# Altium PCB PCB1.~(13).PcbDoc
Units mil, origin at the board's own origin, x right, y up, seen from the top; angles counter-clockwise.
Board outline 6000 x 4000 mil, 2 copper layers (Top Layer, Bottom Layer); 32 components, 21 nets, 142 pads, 0 vias.
Unrouted connection lines stored in the file: 66.
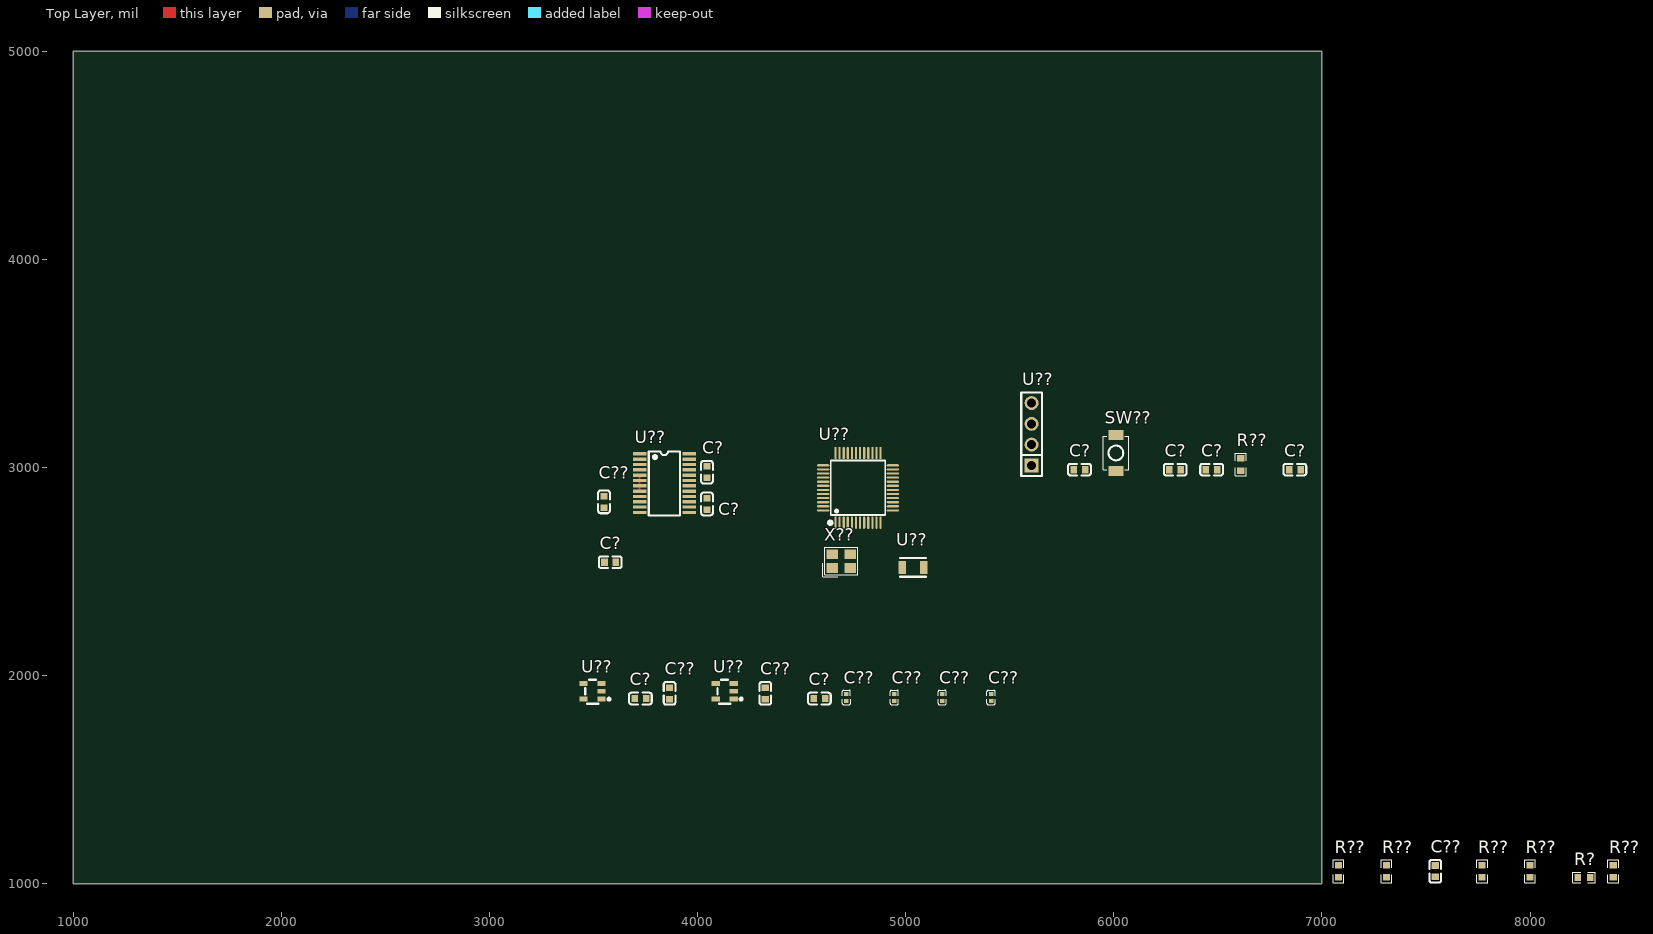
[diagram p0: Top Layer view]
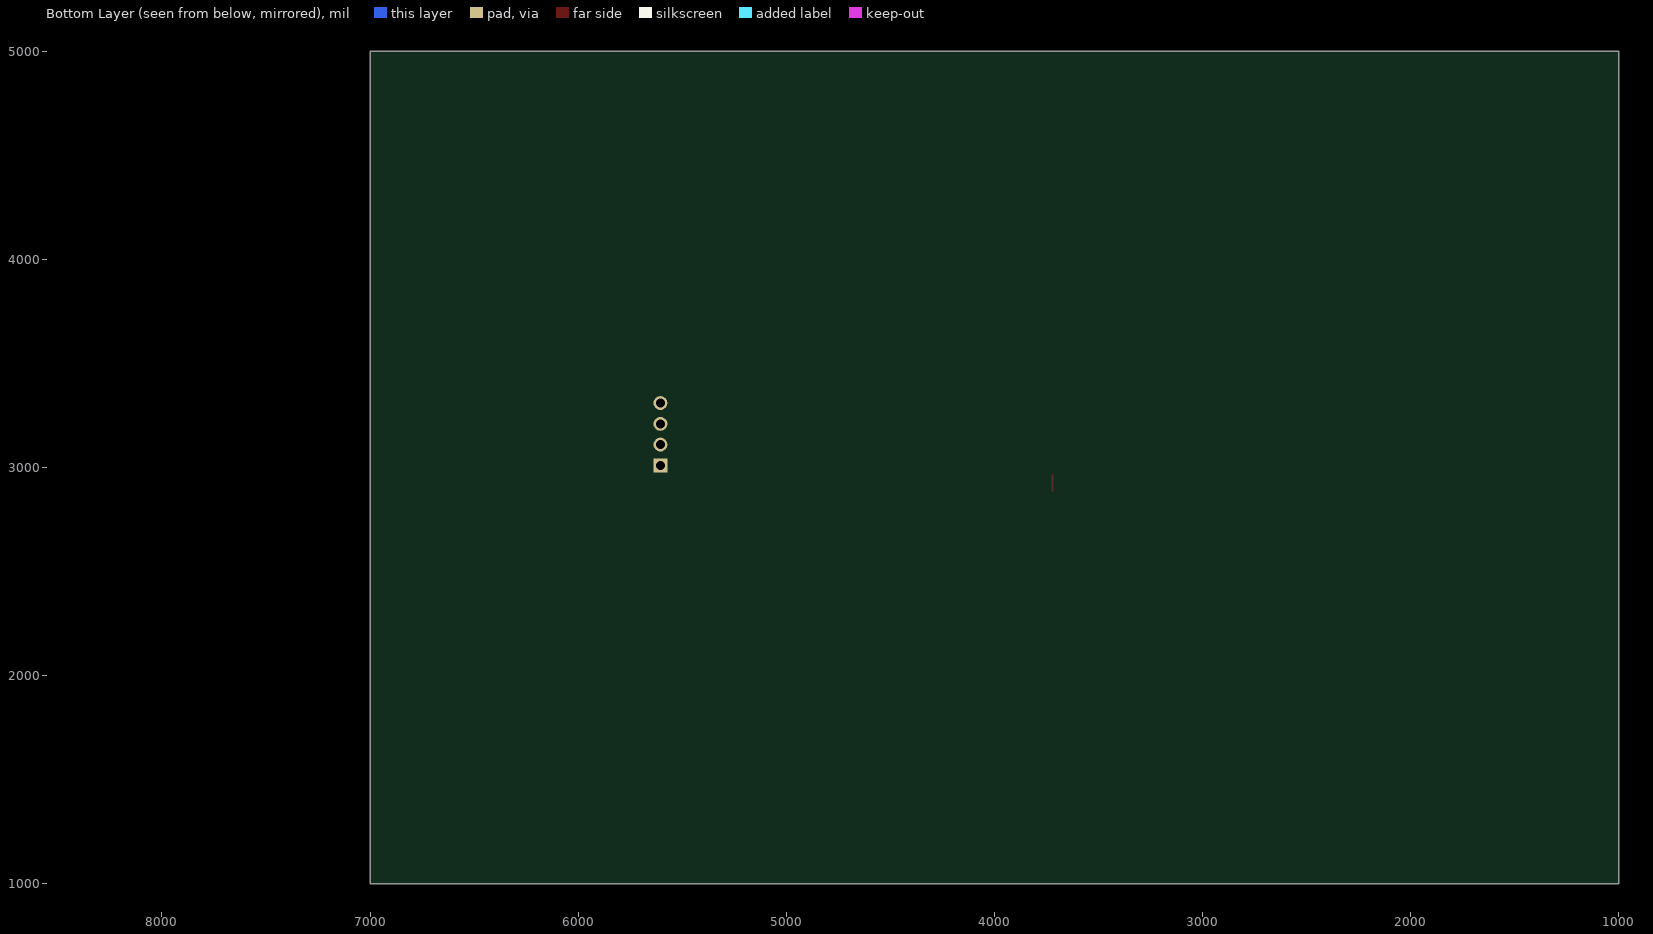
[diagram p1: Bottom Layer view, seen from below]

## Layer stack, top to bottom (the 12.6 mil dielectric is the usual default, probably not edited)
Top Solder: solder mask 0.4, Solder Resist, Dk 3.5
Top Layer: signal copper 1.4
Dielectric 1: dielectric 12.6, FR-4, Dk 4.8
Bottom Layer: signal copper 1.4
Bottom Solder: solder mask 0.4, Solder Resist, Dk 3.5

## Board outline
1000,1000 7000,1000 7000,5000 1000,5000

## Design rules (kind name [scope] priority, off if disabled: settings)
Clearance [All] p1: gap=10 ignorepadtopadclearanceinfootprint=FALSE
PolygonConnect [All] p1: connectstyle=Relief reliefconductorwidth=10 reliefentries=4 polygonreliefangle="90 Angle" airgapwidth=10
RoutingVias [All] p1: holewidth=28 width=50 viastyle="Through Hole" minholewidth=28 minwidth=50 maxholewidth=28 maxwidth=50
SolderMaskExpansion [All] p1: expansion=0 istentingtop=FALSE
SupplyNets "Schematic Supply Nets" [InNet('3V3')] p1: voltage=0.000
SupplyNets "Schematic Supply Nets_6" [InNet('+6')] p2: voltage=0.000
SupplyNets "Schematic Supply Nets_4" [InNet('5V')] p3: voltage=0.000
SupplyNets "Schematic Supply Nets_3" [InNet('DGND')] p4: voltage=0.000
SupplyNets "Schematic Supply Nets_1" [InNet('AGND')] p5: voltage=0.000
Width [All] p1: maxlimit=10 minlimit=10 preferedwidth=10
30 further rules are at their usual default settings.

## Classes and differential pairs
component class Sheet1: C? C?? R? R?? SW?? U?? X??

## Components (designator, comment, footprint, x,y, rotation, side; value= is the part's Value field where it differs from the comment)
C? "cga0603x7r104k500jt" C0603 6295,2990 r0 top value=100nF
C? "cga0603x7r104k500jt" C0603 5835,2990 r0 top value=100nF
C? "cga0603x7r104k500jt" C0603 6870,2990 r0 top value=100nF
C? "cga0603x7r104k500jt" C0603 6470,2990 r0 top value=100nF
C? "cga0603x5r105k500jt" C0603 4585,1890 r0 top value=1uF
C? "cga0603x5r105k500jt" C0603 3725,1890 r0 top value=1uF
C? "cga0603x7r104k500jt" C0603 4045,2825 r90 top value=100nF
C? "fcc0603b103k500ct" C0603 3580,2545 r0 top value=10nF
C? "cga0603x7r104k500jt" C0603 4045,2977.56 r90 top value=100nF
C?? "fcc0603b103k500ct" C0603 7545,1060 r90 top value=10nF
C?? "cga0603x5r105k500jt" C0603 3865,1915 r90 top value=1uF
C?? "cga0603x5r105k500jt" C0603 4325,1915 r90 top value=1uF
C?? "cc0402jrnpo9bn220" C0402 5410,1895 r90 top value=22pF
C?? "cc0402jrnpo9bn220" C0402 5175,1895 r90 top value=22pF
C?? "cc0402jrnpo9bn180" C0402 4715,1895 r90 top value=18pF
C?? "cc0402jrnpo9bn180" C0402 4945,1895 r90 top value=18pF
C?? "cga0603x7r104k500jt" C0603 3550,2835 r90 top value=100nF
R? "0603waf470jt5e" R0603 8260,1030 r0 top value=47Ω
R?? "frc0603f1000ts" R0603 7310,1060 r90 top value=100Ω
R?? "frc0603f1000ts" R0603 7770,1060 r90 top value=100Ω
R?? "0603waf470jt5e" R0603 8000,1060 r90 top value=47Ω
R?? "0603waf470jt5e" R0603 8400,1060 r90 top value=47Ω
R?? "0603waf0000t5e" R0603 7080,1060 r90 top value=0Ω
R?? "frc0603f1002ts" R0603 6610,3015 r90 top value=10kΩ
SW?? "ts-1088-ar02016" SW-SMD_L3.9-W3.0-P4.45 6010,3070 r90 top
U?? "hx pz2.54-1x4p zz" HDR-TH_4P-P2.54-V-M 5605,3160 r90 top
U?? "tps7a2050pdbvr" SOT-23-5_L2.9-W1.6-P0.95-LS2.8-BR 3495,1925 r0 top
U?? "tps7a2033pdbvr" SOT-23-5_L2.9-W1.6-P0.95-LS2.8-BR 4130,1925 r0 top
U?? "fc31m2-32.768-ntlnndtl" CRYSTAL-SMD_L3.2-W1.5 5035,2520 r0 top value=32.768kHz
U?? "stm32g031c8t6" LQFP-48_L7.0-W7.0-P0.50-LS9.0-BL 4770.79,2902.32 r0 top
U?? "ads1232ipwr" TSSOP-24_L7.8-W4.4-P0.65-LS6.4-BL 3840,2925 r270 top
X?? "x32258mob4si" CRYSTAL-SMD_4P-L3.2-W2.5-BL 4690,2550 r0 top value=8MHz

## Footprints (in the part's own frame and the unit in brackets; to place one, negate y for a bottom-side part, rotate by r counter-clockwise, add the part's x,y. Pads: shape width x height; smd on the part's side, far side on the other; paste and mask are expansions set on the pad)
C0402 [mm]
  rect 0.5x0.54 smd: 1(-0.42,0) 2(0.42,0)
  silkscreen extent -0.87,-0.5 0.87,0.5
C0603 [mm]
  rect 0.8x0.9 smd: 1(-0.7,0) 2(0.7,0)
  silkscreen extent -1.39,-0.71 1.39,0.71
CRYSTAL-SMD_4P-L3.2-W2.5-BL [mm]
  rect 1.4x1.2 smd: 1(-1.1,-0.85) 2(1.1,-0.85) 3(1.1,0.85) 4(-1.1,0.85)
  silkscreen extent -2.26,-1.91 2.03,1.68
CRYSTAL-SMD_L3.2-W1.5 [mm]
  rect 0.95x1.6 smd: 1(-1.308,0) 2(1.308,0)
  silkscreen extent -1.6,-1.14 1.6,1.14
HDR-TH_4P-P2.54-V-M [mm]
  rect 1.7x1.7 hole 1.1: 1(-3.81,0)
  round 1.7 hole 1.1: 2(-1.27,0) 3(1.27,0) 4(3.81,0)
  silkscreen extent -5.08,-1.27 5.08,1.27
LQFP-48_L7.0-W7.0-P0.50-LS9.0-BL [mm]
  oval 0.27x1.5 smd paste+0 mask+0.05: 1(-2.75,-4.25) 2(-2.25,-4.25) 3(-1.75,-4.25) 4(-1.25,-4.25) 5(-0.75,-4.25) 6(-0.25,-4.25) 7(0.25,-4.25) 8(0.75,-4.25) 9(1.25,-4.25) 10(1.75,-4.25) 11(2.25,-4.25) 12(2.75,-4.25) 25(2.75,4.25) 26(2.25,4.25) 27(1.75,4.25) 28(1.25,4.25) 29(0.75,4.25) 30(0.25,4.25) 31(-0.25,4.25) 32(-0.75,4.25) 33(-1.25,4.25) 34(-1.75,4.25) 35(-2.25,4.25) 36(-2.75,4.25)
  oval 1.5x0.27 smd paste+0 mask+0.05: 13(4.25,-2.75) 14(4.25,-2.25) 15(4.25,-1.75) 16(4.25,-1.25) 17(4.25,-0.75) 18(4.25,-0.25) 19(4.25,0.25) 20(4.25,0.75) 21(4.25,1.25) 22(4.25,1.75) 23(4.25,2.25) 24(4.25,2.75) 37(-4.25,2.75) 38(-4.25,2.25) 39(-4.25,1.75) 40(-4.25,1.25) 41(-4.25,0.75) 42(-4.25,0.25) 43(-4.25,-0.25) 44(-4.25,-0.75) 45(-4.25,-1.25) 46(-4.25,-1.75) 47(-4.25,-2.25) 48(-4.25,-2.75)
  silkscreen extent -3.59,-4.46 3.3,3.34
R0603 [mil]
  rect 31.75x34.02 smd paste-3937.01 mask+2: 1(-29.66,0) 2(29.66,0)
  silkscreen extent -55,-26 55,26
SOT-23-5_L2.9-W1.6-P0.95-LS2.8-BR [mm]
  rect 1x0.6 smd paste+0 mask+0.05: 1(1.1,-0.95) 2(1.1,0) 3(1.1,0.95) 4(-1.1,0.95) 5(-1.1,-0.95)
  silkscreen extent -0.89,-1.52 2.16,1.4
SW-SMD_L3.9-W3.0-P4.45 [mm]
  rect 1.23x1.86 smd: 1(-2.185,0) 2(2.185,0)
  silkscreen extent -2.03,-1.54 2.03,1.54
TSSOP-24_L7.8-W4.4-P0.65-LS6.4-BL [mm]
  rect 0.4x1.65 smd: 1(-3.575,-3.023) 2(-2.925,-3.023) 3(-2.275,-3.023) 4(-1.625,-3.023) 5(-0.975,-3.023) 6(-0.325,-3.023) 7(0.325,-3.023) 8(0.975,-3.023) 9(1.625,-3.023) 10(2.275,-3.023) 11(2.925,-3.023) 12(3.575,-3.023) 13(3.575,3.023) 14(2.925,3.023) 15(2.275,3.023) 16(1.625,3.023) 17(0.975,3.023) 18(0.325,3.023) 19(-0.325,3.023) 20(-0.975,3.023) 21(-1.625,3.023) 22(-2.275,3.023) 23(-2.925,3.023) 24(-3.575,3.023)
  silkscreen extent -3.89,-1.91 3.94,1.91

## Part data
C? C? C? C? C? C? C??: "容值:100nF;精度:±10%;额定电压:50V;温度系数:X7R;", JLCPCB Part Class="Extended Part", LCSC Part Name="100nF ±10% 50V", Manufacturer=HRE(芯声), ManufacturerPart=CGA0603X7R104K500JT, Temperature Coefficient=X7R, Tolerance=±10%, Voltage Rating=50V
C? C? C?? C??: "容值:1uF;精度:±10%;额定电压:50V;温度系数:X5R;", JLCPCB Part Class="Extended Part", LCSC Part Name="1uF ±10% 50V 停产", Manufacturer=HRE(芯声), ManufacturerPart=CGA0603X5R105K500JT, Temperature Coefficient=X5R, Tolerance=±10%, Voltage Rating=50V
C? C??: "容值:10nF;精度:±10%;额定电压:50V;温度系数:X7R;", JLCPCB Part Class="Extended Part", LCSC Part Name="10nF ±10% 50V", Manufacturer=FOJAN(富捷), ManufacturerPart=FCC0603B103K500CT, Operating Temperature=-55℃~+125℃, Temperature Coefficient=X7R, Tolerance=±10%, Voltage Rating=50V
C?? C??: "容值:22pF;精度:±5%;额定电压:50V;温度系数:NP0;", JLCPCB Part Class="Extended Part", LCSC Part Name="22pF ±5% 50V", Manufacturer=YAGEO(国巨), ManufacturerPart=CC0402JRNPO9BN220, Temperature Coefficient=NP0, Tolerance=±5%, Voltage Rating=50V
C?? C??: "容值:18pF;精度:±5%;额定电压:50V;温度系数:NP0;", JLCPCB Part Class="Extended Part", LCSC Part Name="18pF ±5% 50V", Manufacturer=YAGEO(国巨), ManufacturerPart=CC0402JRNPO9BN180, Temperature Coefficient=NP0, Tolerance=±5%, Voltage Rating=50V
R? R?? R??: "电阻类型:厚膜电阻;阻值:47Ω;精度:±1%;功率:100mW;工作电压:75V;温度系数:±100ppm/℃;", JLCPCB Part Class="Basic Part", LCSC Part Name="47Ω ±1% 100mW 厚膜电阻", Manufacturer=UNI-ROYAL(厚声), ManufacturerPart=0603WAF470JT5E, Operating Temperature=-55℃~+155℃, Power(Watts)=100mW, Temperature Coefficient=±100ppm/℃, Tolerance=±1%, Voltage-Supply(Max)=75V
R?? R??: "电阻类型:厚膜电阻;阻值:100Ω;精度:±1%;功率:100mW;工作电压:75V;温度系数:±100ppm/℃;", JLCPCB Part Class="Extended Part", LCSC Part Name="100Ω ±1% 100mW 厚膜电阻", Manufacturer=FOJAN(富捷), ManufacturerPart=FRC0603F1000TS, Operating Temperature=-55℃~+155℃, Power(Watts)=100mW, Temperature Coefficient=±100ppm/℃, Tolerance=±1%, Voltage-Supply(Max)=75V
R??: "电阻类型:厚膜电阻;阻值:0Ω;精度:±1%;功率:100mW;工作电压:75V;温度系数:-;", JLCPCB Part Class="Basic Part", LCSC Part Name="0Ω ±1% 100mW 厚膜电阻", Manufacturer=UNI-ROYAL(厚声), ManufacturerPart=0603WAF0000T5E, Operating Temperature=-55℃~+155℃, Power(Watts)=100mW, Temperature Coefficient=-, Tolerance=±1%, Voltage-Supply(Max)=75V
R??: "电阻类型:厚膜电阻;阻值:10kΩ;精度:±1%;功率:100mW;工作电压:75V;温度系数:±100ppm/℃;", JLCPCB Part Class="Extended Part", LCSC Part Name="10kΩ ±1% 100mW 厚膜电阻", Manufacturer=FOJAN(富捷), ManufacturerPart=FRC0603F1002TS, Operating Temperature=-55℃~+155℃, Power(Watts)=100mW, Temperature Coefficient=±100ppm/℃, Tolerance=±1%, Voltage-Supply(Max)=75V
SW??: "电路结构:单刀单掷;按钮形状:圆形按钮;作用力:1.6N;安装方式:立贴;开关长度:3.9mm;开关宽度:3mm;开关高度:2mm;带支架:不带支架;触点电流:50mA;额定电压:12V;带灯:-;工作寿命:10万次;", Actuator/Cap Color=黑色, Contact Current=50mA, IP Rating=-, JLCPCB Part Class="Basic Part", LCSC Part Name="3.9*3*2mm 立贴 轻触开关", Manufacturer=XUNPU(讯普), ManufacturerPart=TS-1088-AR02016, Operating Force=1.6N, Operating Temperature=-30℃~+80℃, Voltage Rating=12V
U??: "插针结构:1x4P;间距:2.54mm;行距:-;圆针/方针:方针;安装方式:直插;排数:单排;总PIN位数:4P;额定电流:3A;额定电压:1kV;配合针长度:6mm;塑高:2.5mm;端接针长度:3mm;触头材质:黄铜;触头镀层:金;工作温度:-40℃~+105℃;颜色:黑色;", Color=黑色, Current Rating=3A, JLCPCB Part Class="Extended Part", LCSC Part Name="1x4P 间距:2.54mm 方针 直插", Manufacturer=hanxia(韩下), ManufacturerPart="HX PZ2.54-1x4P ZZ", Operating Temperature=-40℃~+105℃, Voltage Rating (Max)=1kV
U??: "输出极性:正极;工作电压:6V;输出电压:5V;输出电流:300mA;电源纹波抑制比(PSRR):65dB@(100Hz);输出类型:固定;", JLCPCB Part Class="Extended Part", LCSC Part Name="800mV~5.5V 300mA 6V", Manufacturer=TI(德州仪器), ManufacturerPart=TPS7A2050PDBVR, Operating Temperature=-40℃~+125℃@(Tj), Output Current=300mA, Output Voltage=5V, Power Supply Rejection Ratio (PSRR)=65dB@(100Hz), standby current=6.5uA, Voltage - Supply=6V, Voltage Dropout=140mV@(300mA)
U??: "输出类型:固定;最大输入电压:6V;输出电压:3.3V;输出电流:300mA;输出极性:正极;", Dropout Voltage=140mV@(300mA), JLCPCB Part Class="Extended Part", LCSC Part Name="具有高 PSRR 的 300mA、超低噪声、低 IQ、低压降 (LDO) 线性稳压器", Manufacturer=TI(德州仪器), ManufacturerPart=TPS7A2033PDBVR, Maximum Input Voltage=6V, Operating Temperature=-40℃~+125℃@(Tj), Output Current=300mA, Output Voltage=3.3V, standby current=15uA
U??: "晶振类型:贴片晶振;频率:32.768kHz;常温频差:±10ppm;负载电容:12.5pF;频率稳定度:±10ppm;", Equivalent Series Resistance(ESR)=70kΩ, Frequency Stability=±10ppm, JLCPCB Part Class="Extended Part", LCSC Part Name="3215 2P 32.768kHz 12.5pF ±10ppm -40~+85℃(±10ppm)", Load Capacitance=12.5pF, Manufacturer=HCI(杭晶), ManufacturerPart=FC31M2-32.768-NTLNNDTL, Operating Temperature=-40℃~+85℃
U??: "CPU内核:ARM Cortex-M0+;CPU最大主频:64MHz;CPU位数:32 Bit;", JLCPCB Part Class="Extended Part", LCSC Part Name="主流Arm Cortex-M0+ MCU，具有64 KB Flash存储器、8 KB RAM、64 MHz CPU、2x USART、定时器、ADC和通信接口，1.7-3.6V", Manufacturer=ST(意法半导体), ManufacturerPart=STM32G031C8T6, Operating Temperature=-40℃~+85℃, Voltage - Supply=1.7V~3.6V
U??: "分辨率(位):24;采样率:10Hz;工作电压:2.7V~5.3V;接口类型:SPI;", Clock Frequency=4.9152MHz；200kHz~8MHz, JLCPCB Part Class="Extended Part", LCSC Part Name="用于桥式传感器的24bit 模数转换器", Manufacturer=TI(德州仪器), ManufacturerPart=ADS1232IPWR, Operating Temperature=-40℃~+105℃, Quiescent Current (Iq)=1.3uA, Temperature Sensors=内置, Voltage - Supply=2.7V~5.3V, Voltage Reference=外置, Voltage Reference Drift=-
X??: "晶振类型:贴片晶振;频率:8MHz;常温频差:±10ppm;负载电容:12pF;频率稳定度:±20ppm;", Equivalent Series Resistance(ESR)=180Ω, Frequency Stability=±20ppm, JLCPCB Part Class="Extended Part", LCSC Part Name="YSX321SL 8MHZ 4P 3225 12PF ±10PPM -40~85℃ (±20PPM)", Load Capacitance=12pF, Manufacturer=YXC(扬兴晶振), ManufacturerPart=X32258MOB4SI, Normal temperature Frequency Tolerance=±10ppm, Operating Temperature=-40℃~+85℃

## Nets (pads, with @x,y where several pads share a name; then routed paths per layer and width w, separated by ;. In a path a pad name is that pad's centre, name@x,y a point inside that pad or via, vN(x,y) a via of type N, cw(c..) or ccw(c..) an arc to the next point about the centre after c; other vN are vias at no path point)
3V3: C?.1@4045,2950 C?.1@4557.44,1890 C?.2@5862.56,2990 C?.2@6497.56,2990 C?.2@6897.56,2990 R??.2@6610,3044.66 U??.1@3721,3065.74 U??.1@5605,3010 U??.4@4721.58,2735 U??.5@4086.69,1887.6 U??.5@4741.26,2735 U??.6@4760.95,2735 U??.19@3959,2937.79 U??.20@3959,2963.38
5V: C?.1@3552.44,2545 C?.1@3697.44,1890 C?.2@4045,2852.56 U??.5@3451.69,1887.6 U??.16@3959,2861.02 U??.18@3959,2912.21
+6: C??.1@3865,1887.44 C??.1@4325,1887.44 U??.1@3538.31,1887.61 U??.1@4173.31,1887.61 U??.3@3538.31,1962.39 U??.3@4173.31,1962.39
AGND: C?.1@4045,2797.44 C?.2@3607.56,2545 R??.1@7080,1030.34 U??.13@3959,2784.26 U??.14@3959,2809.84 U??.15@3959,2835.43 U??.17@3959,2886.61
AINN1: R??.1@7770,1030.34
AINP1: R??.1@7310,1030.34
DGND: C?.1@5807.44,2990 C?.1@6442.44,2990 C?.1@6842.44,2990 C?.2@3752.56,1890 C?.2@4045,3005.12 C?.2@4612.56,1890 C?.2@6322.56,2990 C??.1@4715,1878.46 C??.1@5175,1878.46 C??.1@5410,1878.46 C??.2@3865,1942.56 C??.2@4325,1942.56 C??.2@4945,1911.54 R??.2@7080,1089.66 SW??.1 U??.2@3538.31,1924.99 U??.2@3721,3040.15 U??.2@4173.31,1924.99 U??.3@3721,3014.56 U??.4@3721,2988.97 U??.4@5605,3310 U??.5@3721,2963.38 U??.6@3721,2937.79 U??.7 U??.8@3721,2886.61 U??.21@3959,2988.97 X??.2 X??.4 | length 76.8
  Top Layer w10: U??.8@3721,2886.61 U??.5@3721,2963.38
DOUT: R??.2@8400,1089.66 U??.19@4938.11,2912.16
NetC??_1: C??.1@3550,2807.44 U??.10@3721,2835.43
NetC??_2: C??.2@3550,2862.56 U??.9@3721,2861.02
NetR??_1: R??.1@8400,1030.34 U??.24@3959,3065.74
NetR?_1: R?.1 U??.23@3959,3040.15
NRST: C?.1@6267.44,2990 R??.1@6610,2985.34 SW??.2 U??.10@4839.69,2735
PDWN: R??.2@8000,1089.66 U??.21@4938.11,2951.53
SCLK: R?.2 U??.20@4938.11,2931.85
SWCLK: U??.3@5605,3210 U??.36
SWDIO: U??.2@5605,3110 U??.35
USART1_RX: U??.32
USART1_TX: U??.29
USART2_RX: U??.14@4938.11,2813.74
USART2_TX: U??.13@4938.11,2794.05
pads on no net: C??.1@4945,1878.46 C??.1@7545,1032.44 C??.2@4715,1911.54 C??.2@5175,1911.54 C??.2@5410,1911.54 C??.2@7545,1087.56 R??.1@8000,1030.34 R??.2@7310,1089.66 R??.2@7770,1089.66 U??.1@4662.52,2735 U??.1@4983.5,2520 U??.2@4682.21,2735 U??.2@5086.5,2520 U??.3@4701.89,2735 U??.4@3451.69,1962.4 U??.4@4086.69,1962.4 U??.8@4800.32,2735 U??.9@4820,2735 U??.11 U??.12 U??.15@4938.11,2833.42 U??.16@4938.11,2853.11 U??.17@4938.11,2872.79 U??.18@4938.11,2892.48 U??.22 U??.23@4938.11,2990.9 U??.24@4938.11,3010.59 U??.25 U??.26 U??.27 U??.28 U??.30 U??.31 U??.33 U??.34 U??.37 U??.38 U??.39 U??.40 U??.41 U??.42 U??.43 U??.44 U??.45 U??.46 U??.47 U??.48 X??.1 X??.3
